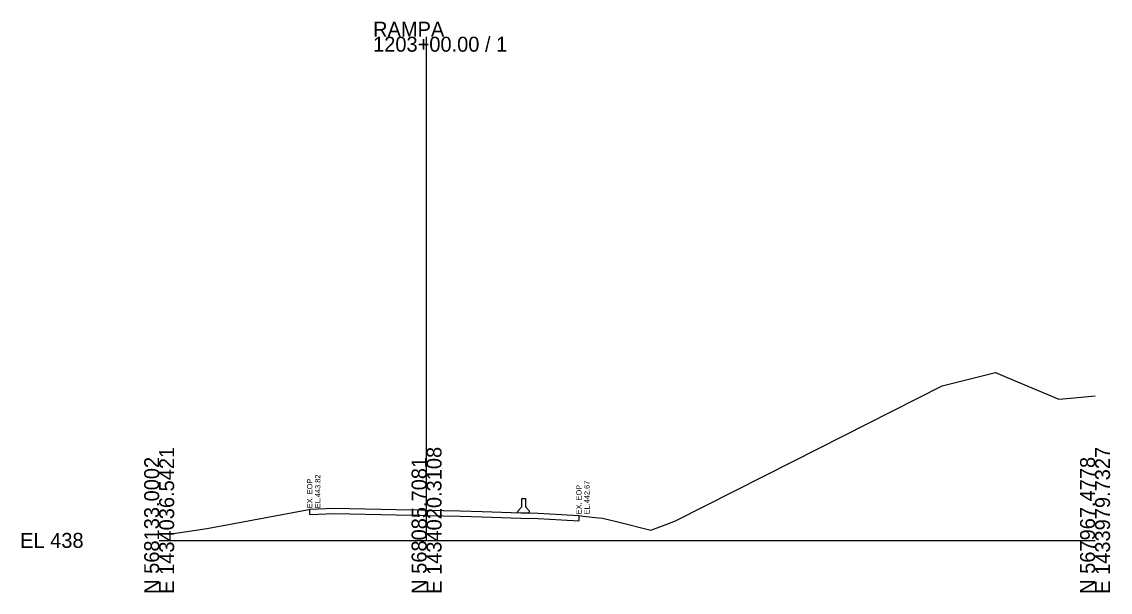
# Model space of a CAD drawing. Extents: x 1431908 to 1449087, y 567604 to 577825.
# Drawn here: x 1431908 to 1432111.5, y 574352.5 to 574459.1 of the extents above; entities that cross this region are included whole.
import ezdxf

# ---------------------------------------------------------------- set-up
doc = ezdxf.new("R2010")
doc.units = 0
for name, color, linetype in [('DESIGN - SHEET - Light Grid', 7, 'Continuous'), ('DESIGN - TYPICAL - Finished Grade and Subgrade', 7, 'Continuous'), ('SURVEY - GROUND - Existing Pavement Layer', 7, 'Continuous'), ('SURVEY - GROUND - Existing Pavement Text', 7, 'Continuous'), ('SURVEY - GROUND - Top of Ground', 7, 'Continuous')]:
    doc.layers.add(name, color=color, linetype=linetype)

msp = doc.modelspace()

# ---------------------------------------------------------------- linework, layer by layer
at = {"layer": 'DESIGN - SHEET - Light Grid'}
for p, q in [((1431983.66, 574362.16), (1431983.66, 574456.33)), ((1431933.66, 574362.16), (1431983.66, 574362.16)), ((1431983.66, 574362.16), (1432108.66, 574362.16))]:
    msp.add_line(p, q, dxfattribs=at)
at = {"layer": 'DESIGN - TYPICAL - Finished Grade and Subgrade'}
for p, q in [((1432001.46, 574368.45), (1432001.48, 574369.91)), ((1432001.58, 574370), (1432002.23, 574369.99)), ((1432002.21, 574368.44), (1432002.23, 574369.99)), ((1432000.69, 574367.46), (1432000.7, 574367.57)), ((1432000.72, 574367.64), (1432001.43, 574368.39)), ((1432000.79, 574367.36), (1432002.84, 574367.32)), ((1432002.92, 574367.6), (1432002.23, 574368.37)), ((1432002.94, 574367.42), (1432002.94, 574367.53))]:
    msp.add_line(p, q, dxfattribs=at)
for centre, start, end in [((1432001.58, 574369.9), 89.0732, 179.0732), ((1432000.79, 574367.46), 179.0732, 269.0732), ((1432000.8, 574367.57), 136.6261, 179.0732), ((1432001.36, 574368.46), 316.6261, 359.0732), ((1432002.31, 574368.44), 179.0732, 221.5203), ((1432002.84, 574367.42), 269.0732, 359.0732), ((1432002.84, 574367.53), 359.0732, 41.5203)]:
    msp.add_arc(centre, 0.1, start, end, dxfattribs=at)
at = {"layer": 'SURVEY - GROUND - Existing Pavement Layer'}
for p, q in [((1431961.81, 574366.97), (1431961.81, 574367.97)), ((1431961.81, 574366.97), (1431966.43, 574367.17)), ((1431966.43, 574367.17), (1431977.95, 574366.96)), ((1431977.95, 574366.96), (1431982.5, 574366.86)), ((1431982.5, 574366.86), (1431983.66, 574366.83)), ((1431983.66, 574366.83), (1431989.88, 574366.7)), ((1431989.88, 574366.7), (1431994.08, 574366.56)), ((1431994.08, 574366.56), (1432001.27, 574366.33)), ((1432001.27, 574366.33), (1432004.56, 574366.22)), ((1432004.56, 574366.22), (1432008.88, 574366)), ((1432008.88, 574366), (1432012.14, 574365.82)), ((1432012.14, 574366.82), (1432012.14, 574365.82))]:
    msp.add_line(p, q, dxfattribs=at)
at = {"layer": 'SURVEY - GROUND - Top of Ground'}
msp.add_lwpolyline([(1431933.66, 574363.5), (1431935.46, 574363.29), (1431940.97, 574364.14), (1431942.96, 574364.44), (1431961.35, 574367.88), (1431961.81, 574367.97), (1431966.43, 574368.17), (1431977.95, 574367.96), (1431982.5, 574367.86), (1431983.66, 574367.83), (1431989.88, 574367.7), (1431994.08, 574367.56), (1432001.27, 574367.33), (1432004.56, 574367.22), (1432008.88, 574367), (1432012.14, 574366.82), (1432012.64, 574366.73), (1432012.94, 574366.67), (1432015.19, 574366.44), (1432016.58, 574366.29), (1432019.2, 574365.67), (1432025.6, 574364.05), (1432027.79, 574364.88), (1432030.23, 574365.83), (1432052.28, 574376.94), (1432080.06, 574391.03), (1432087.32, 574392.85), (1432090.05, 574393.55), (1432092.26, 574392.64), (1432101.91, 574388.55), (1432104.09, 574388.75), (1432108.66, 574389.19)], dxfattribs=at)

# ---------------------------------------------------------------- texts
at = {"layer": 'DESIGN - SHEET - Light Grid'}
for s, p in [('RAMPA', (1431973.66, 574456.33)), ('1203+00.00 / 1', (1431973.66, 574453.53)), ('EL 438', (1431907.66, 574360.76))]:
    msp.add_text(s, height=2.8, dxfattribs=at).set_placement(p)
for s, p in [('E 1434036.5421', (1431936.46, 574352.16)), ('E 1434020.3108', (1431986.46, 574352.16)), ('E 1433979.7327', (1432111.46, 574352.16)), ('N 568133.0002', (1431933.66, 574352.16)), ('N 568085.7081', (1431983.66, 574352.16)), ('N 567967.4778', (1432108.66, 574352.16))]:
    msp.add_text(s, height=2.8, rotation=90, dxfattribs=at).set_placement(p)
at = {"layer": 'SURVEY - GROUND - Existing Pavement Text'}
for s, p in [('EX. EOP', (1431962.31, 574368.17)), ('EL.443.82', (1431963.81, 574368.17)), ('EX. EOP', (1432012.64, 574367.02)), ('EL.442.67', (1432014.14, 574367.02))]:
    msp.add_text(s, height=1, rotation=90, dxfattribs=at).set_placement(p)

doc.saveas('drawing.dxf')
